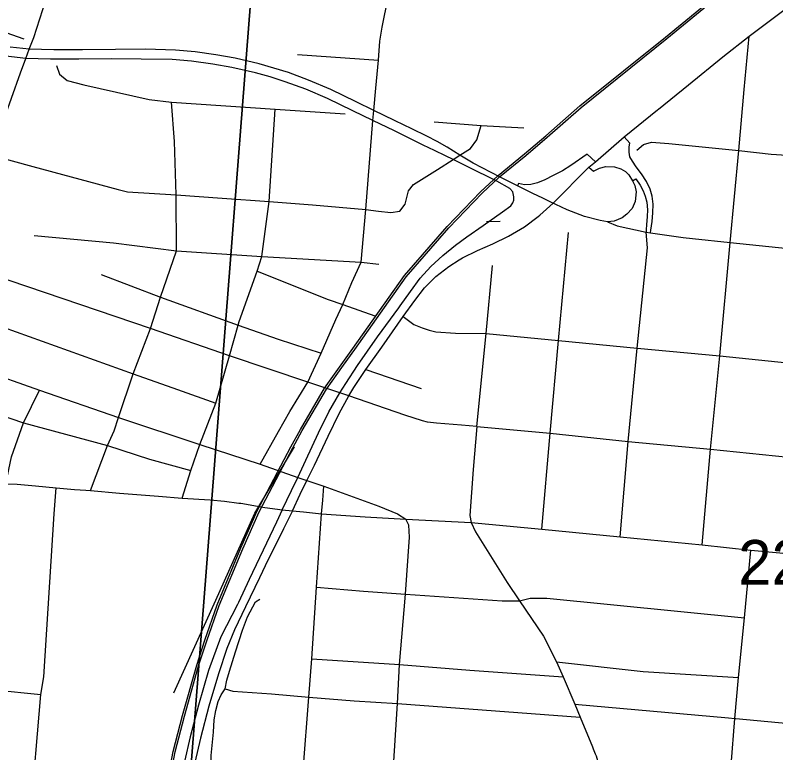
# Model space of a CAD drawing. Extents: x 0 to 34, y 0 to 22.
# Drawn here: x 6.446 to 7.157, y 17.023 to 17.713 of the extents above; entities that cross this region are included whole.
import ezdxf

# ---------------------------------------------------------------- set-up
doc = ezdxf.new("R2010")
doc.units = 0
for name, color, linetype in [('GM_X_City_Street', 7, 'Continuous'), ('GM_X_Corporation', 7, 'Continuous'), ('GM_X_County_Road', 7, 'Continuous'), ('GM_X_Interchange_Ramps', 7, 'Continuous'), ('GM_X_Minor_River', 7, 'Continuous'), ('GM_X_Rail_Line', 7, 'Continuous'), ('GM_X_Section_Text', 7, 'Continuous'), ('GM_X_State_Route', 7, 'Continuous')]:
    doc.layers.add(name, color=color, linetype=linetype)

msp = doc.modelspace()

# ---------------------------------------------------------------- linework, layer by layer
at = {"layer": 'GM_X_City_Street'}
for p, q in [((6.7101, 17.67628), (6.78573, 17.67092)), ((6.77395, 17.38156), (6.82553, 17.36383))]:
    msp.add_line(p, q, dxfattribs=at)
for points in [[(6.45928, 17.68124), (6.46362, 17.69214), (6.47772, 17.73606), (6.49117, 17.77683), (6.49775, 17.79269), (6.51519, 17.82422), (6.53634, 17.86207), (6.55044, 17.88693), (6.56389, 17.91132), (6.56778, 17.92087), (6.57001, 17.92829)], [(6.675, 17.2929), (6.69239, 17.32374), (6.70281, 17.34239), (6.71978, 17.36976), (6.7321, 17.39687), (6.74591, 17.42835), (6.75223, 17.44226), (6.76092, 17.46298), (6.76963, 17.48194), (6.77379, 17.53127), (6.78053, 17.61454), (6.78146, 17.62395), (6.7833, 17.64472), (6.78573, 17.67092), (6.787, 17.68858), (6.78919, 17.70174), (6.79484, 17.7299)], [(6.39837, 17.70991), (6.4204, 17.70272), (6.45416, 17.69094)], [(7.08823, 17.21757), (7.09609, 17.30713), (7.10458, 17.39436), (7.11449, 17.50035), (7.12233, 17.58627), (7.12753, 17.6434), (7.13216, 17.69321)], [(6.48479, 17.66583), (6.48748, 17.65785), (6.49472, 17.65191), (6.51039, 17.64774), (6.57124, 17.63416), (6.59215, 17.63175), (6.68926, 17.62508), (6.75442, 17.62064)], [(6.51657, 17.26837), (6.53248, 17.31047), (6.53868, 17.32417), (6.54256, 17.33658), (6.55651, 17.37751), (6.5725, 17.41977), (6.58183, 17.44932), (6.59691, 17.49257), (6.59668, 17.54497), (6.59505, 17.5947), (6.59215, 17.63175)], [(6.60228, 17.26133), (6.61032, 17.28702), (6.61869, 17.31148), (6.63383, 17.35), (6.64646, 17.39447), (6.65458, 17.42307), (6.65558, 17.4266), (6.6723, 17.47363), (6.67662, 17.48728), (6.68343, 17.53884), (6.68926, 17.62508)], [(6.42356, 17.58203), (6.4626, 17.57148), (6.5424, 17.55006), (6.55128, 17.54785), (6.59668, 17.54497), (6.63961, 17.54181), (6.68343, 17.53884), (6.724, 17.53565), (6.77379, 17.53127), (6.78578, 17.52971), (6.79728, 17.52841), (6.80563, 17.52971), (6.81063, 17.5362), (6.81212, 17.54251), (6.8136, 17.54882), (6.81838, 17.55467), (6.84087, 17.56848), (6.85537, 17.57783), (6.8618, 17.58197), (6.87167, 17.58814), (6.87749, 17.59623), (6.88172, 17.6097)], [(6.83768, 17.6131), (6.88172, 17.6097), (6.92162, 17.60765)], [(7.02712, 17.58661), (7.03333, 17.5919), (7.04076, 17.59404), (7.05693, 17.59288), (7.12233, 17.58627), (7.15275, 17.58311), (7.18689, 17.58089)], [(6.93845, 17.23231), (6.9462, 17.32215), (6.95399, 17.40876), (6.96327, 17.50979)], [(7.01155, 17.22513), (7.01911, 17.31436), (7.02732, 17.4016), (7.037, 17.49525), (7.03591, 17.51014)], [(6.46381, 17.5068), (6.53815, 17.50002), (6.59691, 17.49257), (6.67662, 17.48728), (6.76963, 17.48194), (6.78606, 17.48001)], [(6.23895, 17.49149), (6.24829, 17.48825), (6.27757, 17.47808), (6.35395, 17.44871), (6.36823, 17.44386), (6.37352, 17.44206), (6.41585, 17.42768), (6.4289, 17.42325), (6.4349, 17.42121), (6.55651, 17.37751), (6.59776, 17.36284), (6.63383, 17.35)], [(6.6723, 17.47363), (6.73875, 17.44691), (6.75223, 17.44226), (6.78243, 17.43185)], [(6.87771, 17.32837), (6.88638, 17.41509), (6.89213, 17.47872)], [(6.52663, 17.47057), (6.58183, 17.44932), (6.65458, 17.42307), (6.69191, 17.40994), (6.7321, 17.39687)], [(6.8087, 17.43099), (6.81867, 17.42381), (6.82655, 17.42047), (6.83291, 17.41829), (6.83931, 17.41685), (6.85776, 17.41555), (6.88638, 17.41509), (6.95399, 17.40876), (7.02732, 17.4016), (7.10458, 17.39436), (7.17687, 17.38683), (7.24394, 17.38022), (7.31091, 17.37354)], [(6.37068, 16.58176), (6.38795, 16.61948), (6.39182, 16.66615), (6.39752, 16.73485), (6.40074, 16.77365), (6.40339, 16.80561), (6.40836, 16.86588), (6.41615, 16.96752), (6.42491, 17.08202), (6.43188, 17.17304), (6.4322, 17.17727), (6.43739, 17.27457), (6.44286, 17.29977), (6.45399, 17.33184), (6.46889, 17.36233)], [(6.37388, 17.35811), (6.4162, 17.34443), (6.45399, 17.33184), (6.53248, 17.31047), (6.57155, 17.29782), (6.61032, 17.28702)], [(6.87771, 17.32837), (6.9462, 17.32215), (7.01911, 17.31436), (7.09609, 17.30713), (7.16881, 17.29952), (7.23541, 17.29321), (7.30256, 17.28616)], [(6.45092, 16.84973), (6.45191, 16.86151), (6.4605, 16.96358), (6.4701, 17.0776), (6.47288, 17.09427), (6.48271, 17.24644), (6.4845, 17.27098)], [(6.68284, 16.53638), (6.6843, 16.55627), (6.68463, 16.56766), (6.68496, 16.57904), (6.689, 16.62652), (6.68977, 16.64204), (6.69247, 16.68485), (6.69711, 16.74313), (6.70383, 16.83842), (6.70573, 16.86939), (6.71087, 16.93733), (6.71518, 17.00647), (6.72045, 17.07523), (6.72338, 17.11103), (6.72782, 17.17797), (6.73242, 17.24656), (6.73354, 17.25932), (6.73465, 17.27245)], [(6.76857, 16.56697), (6.77257, 16.61771), (6.7749, 16.67418), (6.77992, 16.7352), (6.78296, 16.7746), (6.78665, 16.83028), (6.78925, 16.86306), (6.79397, 16.93188), (6.79681, 16.97128), (6.79917, 17.00045), (6.80347, 17.06909), (6.80528, 17.10576), (6.81084, 17.17148), (6.81469, 17.22488), (6.81419, 17.23603), (6.81113, 17.24172)], [(7.11542, 17.01164), (7.11887, 17.0553), (7.12204, 17.09351), (7.12772, 17.1493), (7.13358, 17.21262)], [(6.72782, 17.17797), (6.7717, 17.17433), (6.81084, 17.17148), (6.90128, 17.16517), (6.91739, 17.16517), (6.92755, 17.16777), (6.94316, 17.16764), (7.12772, 17.1493)], [(6.64255, 17.08287), (6.64403, 17.09096), (6.64638, 17.09938), (6.65196, 17.11759), (6.65852, 17.13766), (6.66317, 17.15024), (6.67066, 17.16436), (6.67469, 17.16665)], [(6.72338, 17.11103), (6.80528, 17.10576), (6.87098, 17.10051), (6.95821, 17.09401)], [(6.95211, 17.10804), (7.03311, 17.09909), (7.12204, 17.09351)], [(6.33759, 17.09053), (6.33949, 17.09038), (6.38302, 17.08612), (6.42491, 17.08202), (6.42656, 17.08186), (6.4701, 17.0776)], [(6.62932, 17.01235), (6.62929, 17.02053), (6.63155, 17.04233), (6.63204, 17.05385), (6.63362, 17.06277), (6.63591, 17.07113), (6.63861, 17.0772), (6.64255, 17.08287)], [(6.64255, 17.08287), (6.64954, 17.0808), (6.68584, 17.07813), (6.72045, 17.07523), (6.7629, 17.07182), (6.80347, 17.06909), (6.9743, 17.05639)], [(6.96935, 17.06844), (7.11291, 17.05582), (7.11887, 17.0553), (7.11962, 17.05523), (7.18935, 17.04868)]]:
    msp.add_lwpolyline(points, dxfattribs=at)
at = {"layer": 'GM_X_Corporation'}
for points in [[(6.66967, 17.77276), (6.59067, 16.75631), (5.54549, 16.85525), (5.58671, 17.52328), (5.56589, 17.57675), (5.57345, 17.59363), (5.59139, 17.63529), (5.60336, 17.66382), (5.61551, 17.69993), (6.08674, 17.82542)], [(6.66967, 17.77276), (7.71609, 17.66356), (7.61007, 16.65134), (6.59067, 16.75631)]]:
    msp.add_lwpolyline(points, close=True, dxfattribs=at)
at = {"layer": 'GM_X_County_Road'}
for p, q in [((6.75786, 17.35695), (6.74959, 17.35973)), ((6.81113, 17.24172), (6.87229, 17.23851))]:
    msp.add_line(p, q, dxfattribs=at)
for points in [[(7.13216, 17.69321), (7.16574, 17.71853), (7.20491, 17.74226), (7.20576, 17.74272)], [(7.04749, 17.62517), (7.07535, 17.64767), (7.10744, 17.67406), (7.13216, 17.69321)], [(6.38826, 17.4828), (6.40417, 17.52939), (6.42356, 17.58203), (6.42561, 17.58786), (6.45112, 17.65905), (6.45599, 17.67231), (6.45928, 17.68124)], [(6.98241, 17.57082), (6.98842, 17.57589), (7.01536, 17.59909), (7.04646, 17.62434), (7.04749, 17.62517)], [(6.74959, 17.35973), (6.71978, 17.36976), (6.64646, 17.39447), (6.5725, 17.41977), (6.44144, 17.46448), (6.38826, 17.4828), (6.32286, 17.50224), (6.28418, 17.5186), (6.2793, 17.52138)], [(6.99971, 17.51981), (7.00862, 17.51605), (7.03591, 17.51014), (7.04003, 17.50954), (7.07039, 17.50515), (7.07921, 17.50419)], [(7.07921, 17.50419), (7.11449, 17.50035), (7.1867, 17.49275), (7.2477, 17.48495), (7.25351, 17.48438), (7.31196, 17.4786)], [(6.35698, 17.39892), (6.38618, 17.38915), (6.41408, 17.38148), (6.46889, 17.36233), (6.54256, 17.33658), (6.61869, 17.31148), (6.675, 17.2929), (6.71036, 17.28071), (6.71875, 17.27782)], [(6.87771, 17.32837), (6.86333, 17.32953), (6.83996, 17.33143), (6.83165, 17.33222), (6.82669, 17.33365), (6.8104, 17.33899), (6.75786, 17.35695)], [(6.87771, 17.32837), (6.87404, 17.28811), (6.87107, 17.24489), (6.87229, 17.23851)], [(6.29431, 17.31834), (6.32138, 17.30993), (6.35454, 17.29768), (6.3667, 17.29357), (6.38012, 17.28899), (6.39026, 17.28506), (6.41022, 17.27868), (6.42413, 17.27606), (6.43739, 17.27457), (6.44801, 17.27442), (6.46503, 17.27279), (6.4845, 17.27098), (6.50168, 17.26935), (6.51232, 17.26865)], [(6.71875, 17.27782), (6.73465, 17.27245), (6.78607, 17.25375), (6.80354, 17.24656), (6.81113, 17.24172)], [(6.51232, 17.26865), (6.51657, 17.26837), (6.54373, 17.26591), (6.58022, 17.26297), (6.60228, 17.26133), (6.62826, 17.25963), (6.64174, 17.25839), (6.6551, 17.2567)], [(6.6551, 17.2567), (6.65716, 17.25644), (6.67943, 17.25248), (6.69132, 17.25093), (6.69564, 17.25029)], [(6.69564, 17.25029), (6.70519, 17.24934), (6.71548, 17.24832), (6.73242, 17.24656), (6.77339, 17.24371), (6.81113, 17.24172)], [(6.87229, 17.23851), (6.93845, 17.23231), (7.01155, 17.22513), (7.08823, 17.21757), (7.13358, 17.21262), (7.16071, 17.21014), (7.22748, 17.20246), (7.25945, 17.19936), (7.29488, 17.19577), (7.37293, 17.18796), (7.4859, 17.17808), (7.53111, 17.17328), (7.5518, 17.17105), (7.61596, 17.16422), (7.69767, 17.15662), (7.75624, 17.15156), (7.7976, 17.148), (7.83515, 17.14475), (7.90889, 17.1384), (7.99909, 17.13062), (8.02795, 17.12813)], [(6.87229, 17.23851), (6.87645, 17.22977), (6.90599, 17.18251), (6.91739, 17.16517), (6.93983, 17.13217), (6.95211, 17.10804), (6.95821, 17.09401), (6.96935, 17.06844), (6.9743, 17.05639), (6.9857, 17.02862), (6.98645, 17.0268)], [(6.98645, 17.0268), (6.98833, 17.02224), (6.9891, 17.02035), (6.99851, 16.98683), (7.00034, 16.96176), (7.00103, 16.95948), (7.01573, 16.91627), (7.01878, 16.90103), (7.02172, 16.89135), (7.029, 16.86155), (7.0352, 16.84626), (7.03824, 16.82787), (7.04546, 16.81363), (7.05634, 16.80097), (7.05779, 16.79954)]]:
    msp.add_lwpolyline(points, dxfattribs=at)
at = {"layer": 'GM_X_Interchange_Ramps'}
for points in [[(7.04003, 17.50954), (7.04038, 17.51199), (7.04159, 17.51992), (7.04224, 17.52818), (7.04252, 17.5362), (7.04154, 17.54353), (7.03946, 17.55035), (7.03626, 17.5573), (7.03143, 17.56472), (7.02666, 17.57099), (7.02299, 17.57632), (7.02072, 17.58049), (7.01993, 17.58485), (7.01998, 17.58972), (7.02063, 17.5932), (7.01536, 17.59909)], [(6.98842, 17.57589), (6.98067, 17.58306), (6.96539, 17.57224), (6.95767, 17.56735), (6.94884, 17.56292), (6.94114, 17.55911), (6.93418, 17.55624), (6.92806, 17.55448), (6.92231, 17.5542), (6.91665, 17.5555), (6.91556, 17.5535)], [(7.02317, 17.558), (7.0261, 17.55981), (7.03037, 17.55387), (7.0331, 17.54877), (7.03505, 17.54358), (7.03658, 17.53806), (7.03723, 17.53101), (7.03695, 17.52452), (7.03626, 17.51691), (7.03593, 17.51237), (7.03591, 17.51014)]]:
    msp.add_lwpolyline(points, dxfattribs=at)
at = {"layer": 'GM_X_Minor_River'}
msp.add_lwpolyline([(6.89935, 17.51988), (6.88679, 17.51979)], dxfattribs=at)
at = {"layer": 'GM_X_Rail_Line'}
for points in [[(6.75298, 17.38558), (6.76344, 17.4003), (6.81164, 17.46836), (6.85131, 17.51393), (6.88247, 17.54646), (6.89869, 17.5617), (6.92355, 17.58176), (6.94321, 17.59879), (6.97526, 17.62665), (7.05517, 17.69106), (7.14534, 17.76525), (7.22662, 17.83216), (7.28553, 17.87707), (7.50511, 18.05291)], [(6.58357, 16.97031), (6.5939, 17.02432), (6.60242, 17.05792), (6.61579, 17.10509), (6.62334, 17.12846), (6.63489, 17.16162), (6.65715, 17.21467), (6.67236, 17.24927), (6.70392, 17.30934), (6.71283, 17.32548), (6.73536, 17.3641), (6.76184, 17.40135), (6.81012, 17.46954), (6.84989, 17.51522), (6.88111, 17.54781), (6.89742, 17.56314), (6.92231, 17.58322), (6.94195, 17.60023), (6.97402, 17.62811), (7.05395, 17.69254), (7.14412, 17.76673), (7.22543, 17.83366)], [(6.56935, 16.22599), (6.56862, 16.37274), (6.56838, 16.55191), (6.56877, 16.59764), (6.56912, 16.65097), (6.56919, 16.69026), (6.56925, 16.74758), (6.56938, 16.79919), (6.5701, 16.83385), (6.57296, 16.88538), (6.57859, 16.93007), (6.58546, 16.96997), (6.59578, 17.0239), (6.60427, 17.05743), (6.61763, 17.10453), (6.62516, 17.12786), (6.63669, 17.16094), (6.65892, 17.21392), (6.67409, 17.24845), (6.70561, 17.30844), (6.7145, 17.32453), (6.73698, 17.36306), (6.75298, 17.38558)], [(6.59451, 17.07929), (6.62315, 17.14238), (6.63366, 17.16592), (6.66998, 17.24726), (6.70733, 17.30924)]]:
    msp.add_lwpolyline(points, dxfattribs=at)
at = {"layer": 'GM_X_State_Route'}
msp.add_line((6.9513, 17.53604), (6.949, 17.53713), dxfattribs=at)
for points in [[(6.9487, 17.53727), (6.94304, 17.53998), (6.93935, 17.54176), (6.92992, 17.54629), (6.91804, 17.55218), (6.91556, 17.5535), (6.89954, 17.5615), (6.87414, 17.5747), (6.8618, 17.58197), (6.84975, 17.58956), (6.84039, 17.59489), (6.83097, 17.59967), (6.81673, 17.60681), (6.80135, 17.61429), (6.80081, 17.61455), (6.78146, 17.62395), (6.76498, 17.63195), (6.74114, 17.64354), (6.72036, 17.65226), (6.70172, 17.65931), (6.67417, 17.66747), (6.65173, 17.67262), (6.63382, 17.67596), (6.61439, 17.67856), (6.59612, 17.68013), (6.56806, 17.68106), (6.53982, 17.68097), (6.50902, 17.68069), (6.4824, 17.68064), (6.45928, 17.68124), (6.44141, 17.6831)], [(6.91224, 17.54321), (6.91132, 17.5476), (6.9086, 17.55077), (6.89631, 17.55787), (6.86913, 17.57109), (6.85537, 17.57783), (6.84841, 17.5813), (6.83808, 17.58644), (6.82758, 17.59152), (6.80069, 17.60467), (6.78053, 17.61454), (6.7616, 17.6236), (6.73812, 17.63505), (6.71774, 17.64388), (6.69849, 17.65069), (6.68455, 17.65534), (6.67071, 17.65908), (6.64876, 17.66399), (6.6309, 17.66728), (6.61089, 17.66994), (6.59285, 17.67157), (6.56377, 17.67197), (6.53654, 17.67203), (6.50574, 17.67175), (6.47912, 17.67171), (6.45599, 17.67231), (6.43742, 17.67461)], [(6.93488, 17.52477), (6.93648, 17.52598), (6.94886, 17.53719), (6.98241, 17.57082)], [(6.98241, 17.57082), (6.9868, 17.56704), (6.99215, 17.57001), (6.99832, 17.57145), (7.0063, 17.57099), (7.01228, 17.56922), (7.01641, 17.56663), (7.01965, 17.56379), (7.02317, 17.558), (7.02515, 17.55355), (7.02644, 17.54789), (7.02547, 17.53869), (7.02273, 17.53207), (7.01775, 17.52683), (7.01353, 17.52352), (7.00611, 17.52041), (6.99971, 17.51981)], [(6.80604, 17.44115), (6.81569, 17.45457), (6.82475, 17.46715), (6.83474, 17.47783), (6.84582, 17.48827), (6.85766, 17.49792), (6.86814, 17.50555), (6.88343, 17.5163), (6.90167, 17.52892), (6.90932, 17.53453), (6.91123, 17.53736), (6.91225, 17.53991), (6.91224, 17.54321)], [(6.99971, 17.51981), (6.99276, 17.52088), (6.97815, 17.52454), (6.96205, 17.53099), (6.9513, 17.53604)], [(6.86101, 17.48399), (6.86422, 17.486), (6.87823, 17.49286), (6.89265, 17.49912), (6.90731, 17.50622), (6.9221, 17.51508), (6.93488, 17.52477)], [(6.8087, 17.43099), (6.81952, 17.44621), (6.82865, 17.4578), (6.83941, 17.46847), (6.85138, 17.47798), (6.86101, 17.48399)], [(6.69564, 17.25029), (6.70449, 17.26845), (6.71036, 17.28071), (6.71775, 17.29689), (6.72953, 17.32229), (6.73923, 17.34203), (6.74959, 17.35973), (6.75513, 17.36853), (6.76618, 17.38526), (6.78476, 17.41216), (6.80461, 17.43916), (6.80604, 17.44115)], [(6.70519, 17.24934), (6.71247, 17.26506), (6.71875, 17.27782), (6.72574, 17.29224), (6.73882, 17.31923), (6.74902, 17.34033), (6.75786, 17.35695), (6.76273, 17.36477), (6.77395, 17.38156), (6.7888, 17.40248), (6.8087, 17.43099)], [(6.29431, 17.31834), (6.32138, 17.30993), (6.35454, 17.29768), (6.3667, 17.29357), (6.38012, 17.28899), (6.39026, 17.28506), (6.41022, 17.27868), (6.42413, 17.27606), (6.43739, 17.27457), (6.44801, 17.27442), (6.46503, 17.27279), (6.4845, 17.27098), (6.50168, 17.26935), (6.51232, 17.26865)], [(6.51232, 17.26865), (6.51657, 17.26837), (6.54373, 17.26591), (6.58022, 17.26297), (6.60228, 17.26133), (6.62826, 17.25963), (6.64174, 17.25839), (6.6551, 17.2567)], [(6.6551, 17.2567), (6.65716, 17.25644), (6.67943, 17.25248), (6.69132, 17.25093), (6.69564, 17.25029)], [(6.70519, 17.24934), (6.69684, 17.23269), (6.68973, 17.21794), (6.68273, 17.2038), (6.67443, 17.18669), (6.6613, 17.15965), (6.65101, 17.13799), (6.64386, 17.12055), (6.63617, 17.09685), (6.62728, 17.06673), (6.61935, 17.03687), (6.61406, 17.01401)], [(6.69564, 17.25029), (6.69024, 17.23886), (6.68107, 17.2193), (6.66497, 17.18525), (6.65493, 17.16368), (6.65404, 17.16194)], [(6.65404, 17.16194), (6.63845, 17.13147), (6.62681, 17.10012), (6.61752, 17.06779), (6.60959, 17.03793), (6.60429, 17.01507), (6.6002, 16.99488), (6.595, 16.96738), (6.59227, 16.94576), (6.5911, 16.91466), (6.59023, 16.88902), (6.58918, 16.84914), (6.58843, 16.81641), (6.58633, 16.77683), (6.58516, 16.75291), (6.58471, 16.73048), (6.58308, 16.70063), (6.58352, 16.67675), (6.58656, 16.65678), (6.59122, 16.64104), (6.59947, 16.62303), (6.61423, 16.6024), (6.62596, 16.58938), (6.63256, 16.58347)]]:
    msp.add_lwpolyline(points, dxfattribs=at)

# ---------------------------------------------------------------- texts
at = {"layer": 'GM_X_Section_Text'}
msp.add_text('22', height=0.041856, rotation=0.00001, dxfattribs=at).set_placement((7.12187, 17.18026))

doc.saveas('drawing.dxf')
